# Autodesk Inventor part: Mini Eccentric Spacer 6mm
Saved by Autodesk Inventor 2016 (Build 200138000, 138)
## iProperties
Created: 2016-03
Part Number: Mini Eccentric Spacer 6mm
Material: Generic
Document SubType Name: Modeling
Designer: bongo_000
Density: 1 g/cm^3
Appearance: Default
Author: bongo_000
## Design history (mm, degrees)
feature "CUT-REVOLVE1"
body "Solid1"
